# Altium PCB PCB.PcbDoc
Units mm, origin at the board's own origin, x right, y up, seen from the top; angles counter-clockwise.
Board outline 65 x 50 mm, 2 copper layers (Top Layer, Bottom Layer); 114 components, 86 nets, 390 pads, 295 vias.
Unrouted connection lines stored in the file: 2.
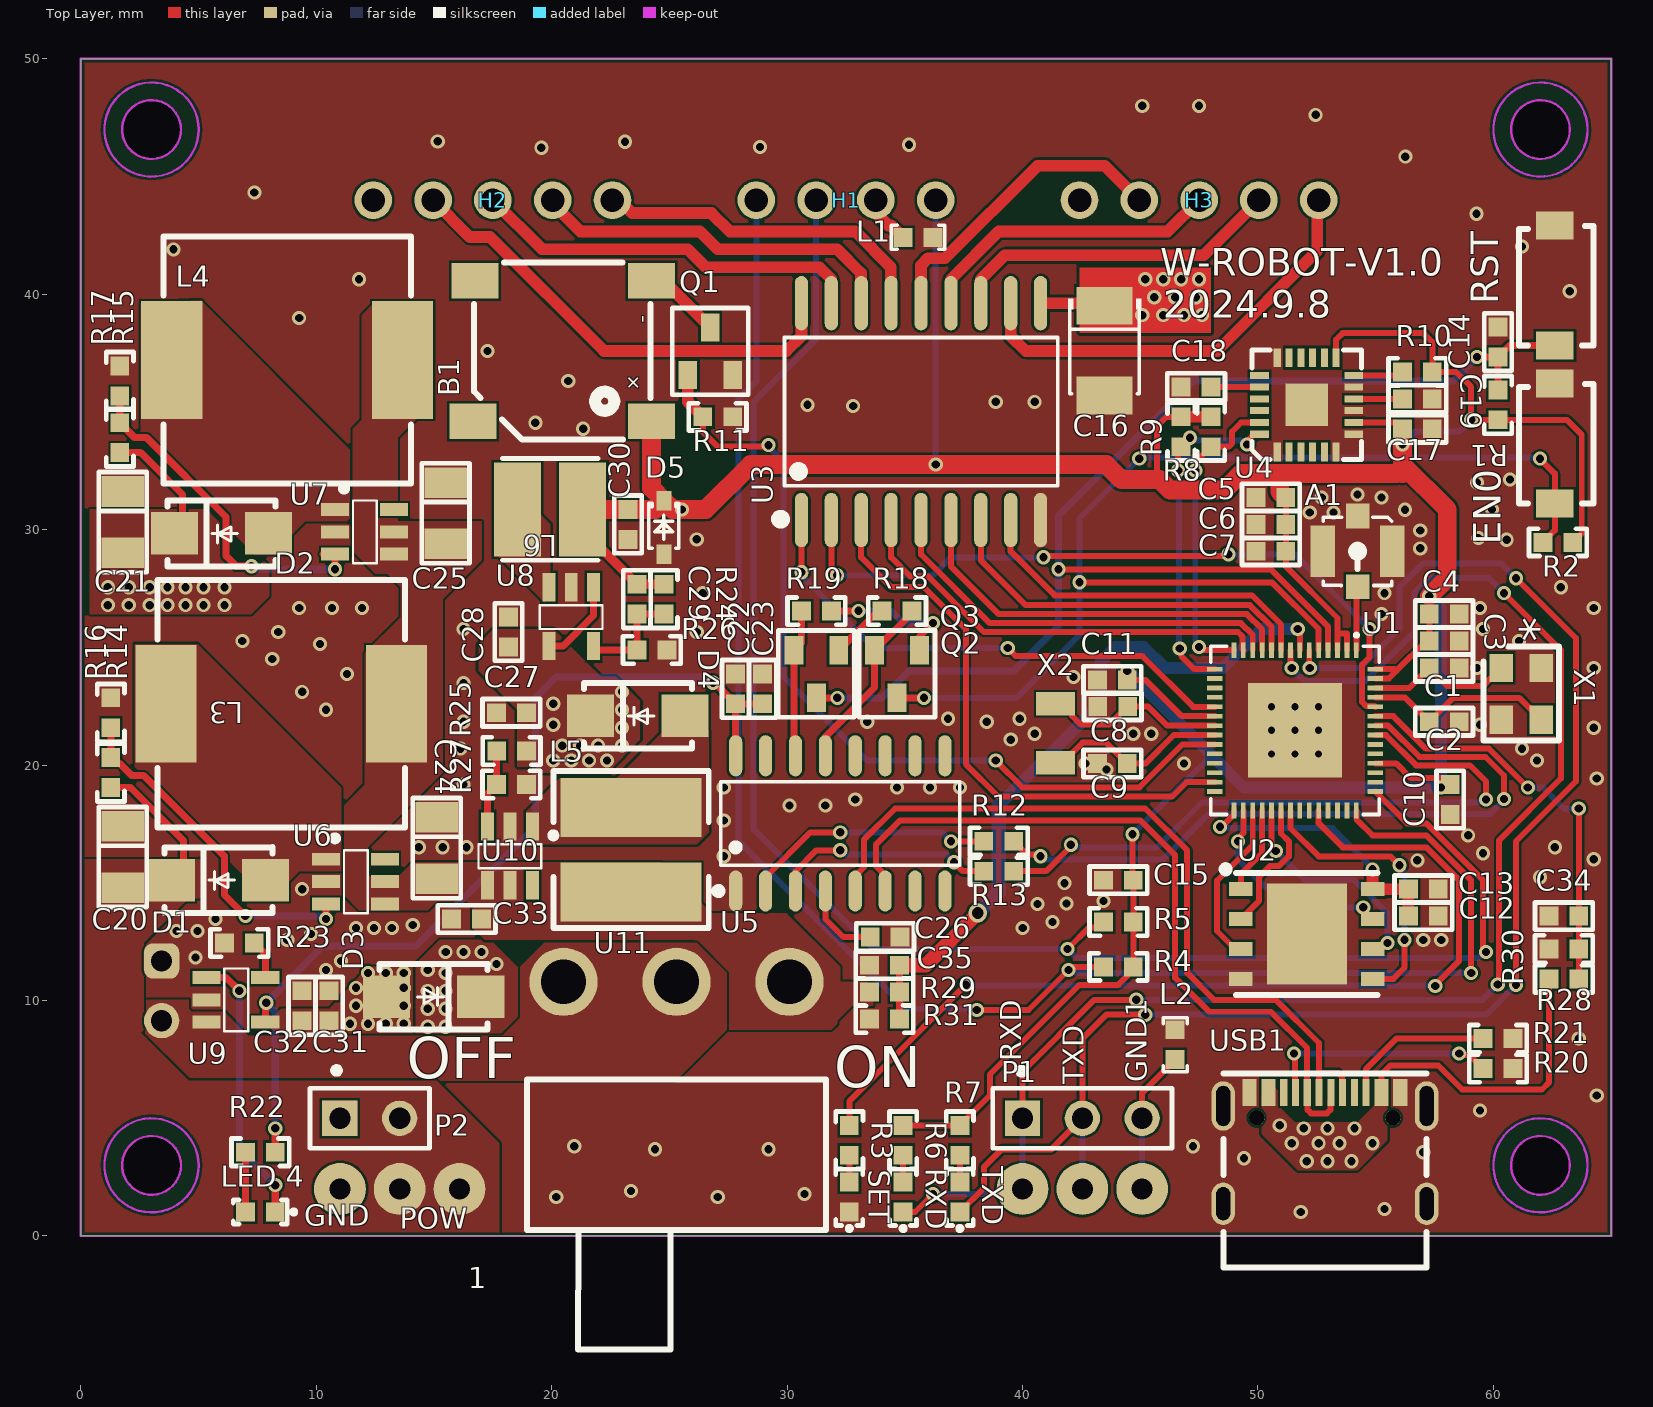
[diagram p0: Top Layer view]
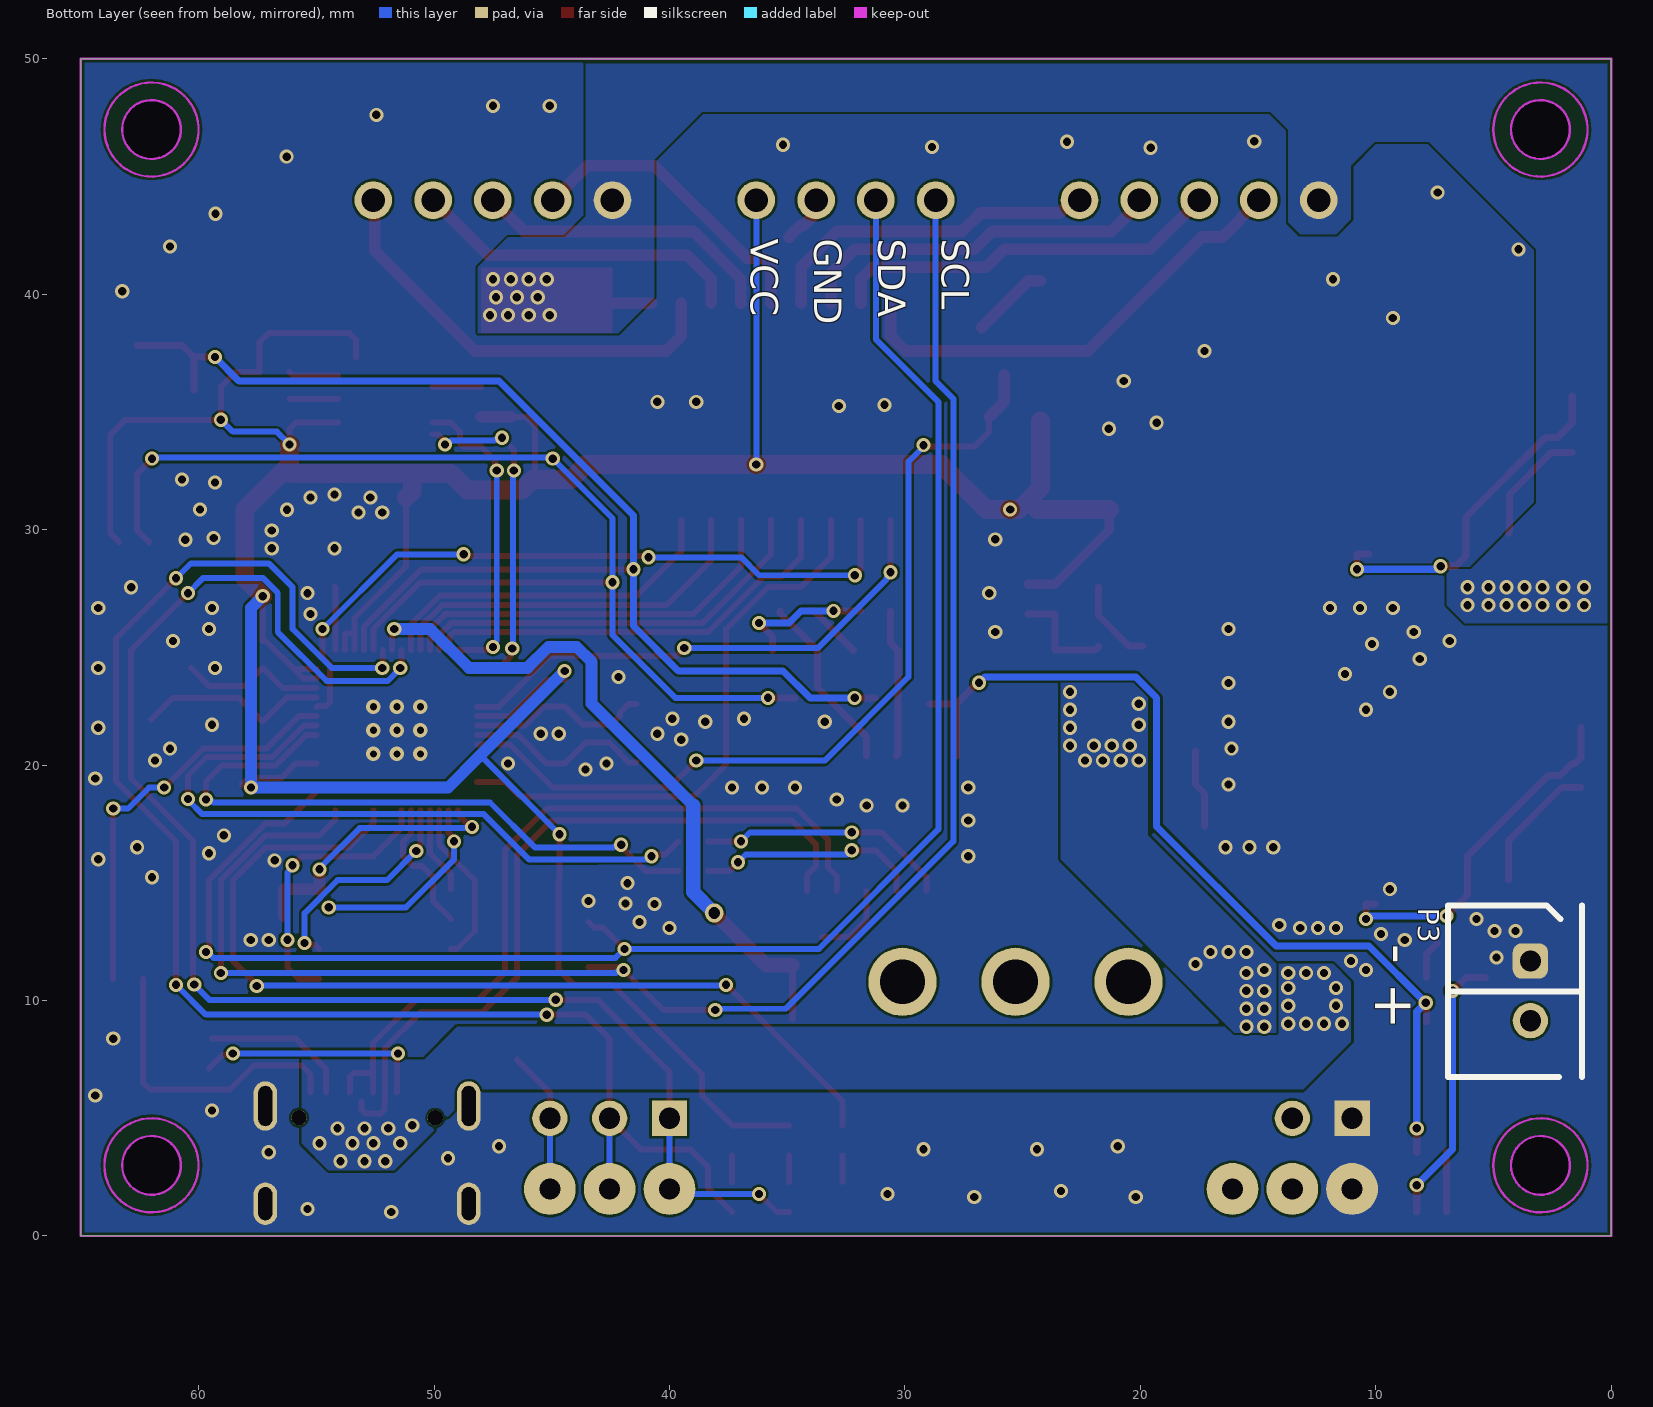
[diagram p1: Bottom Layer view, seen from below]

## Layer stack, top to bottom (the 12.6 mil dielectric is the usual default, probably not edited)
Top Solder: solder mask 0.0102, Solder Resist, Dk 3.5
Top Layer: signal copper 0.0356
Dielectric 1: dielectric 0.32, FR-4, Dk 4.8
Bottom Layer: signal copper 0.0356
Bottom Solder: solder mask 0.0102, Solder Resist, Dk 3.5

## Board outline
0,0 0,50 65,50 65,0
cut-out: 60.75,47 ccw(c62,47) 62,45.75 ccw(c62,47) 63.25,47 ccw(c62,47) 62,48.25 ccw(c62,47)
cut-out: 60.75,3 ccw(c62,3) 62,1.75 ccw(c62,3) 63.25,3 ccw(c62,3) 62,4.25 ccw(c62,3)
cut-out: 60.75,3 ccw(c62,3) 62,1.75 ccw(c62,3) 63.25,3 ccw(c62,3) 62,4.25 ccw(c62,3)
cut-out: 60.75,3 ccw(c62,3) 62,1.75 ccw(c62,3) 63.25,3 ccw(c62,3) 62,4.25 ccw(c62,3)
cut-out: 1.75,3 ccw(c3,3) 3,1.75 ccw(c3,3) 4.25,3 ccw(c3,3) 3,4.25 ccw(c3,3)
cut-out: 1.75,47 ccw(c3,47) 3,45.75 ccw(c3,47) 4.25,47 ccw(c3,47) 3,48.25 ccw(c3,47)

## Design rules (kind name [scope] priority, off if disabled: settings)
Clearance [All] p1: gap=0.1 ignorepadtopadclearanceinfootprint=FALSE except(0: Arc-Hole Track-Hole SMDPad-Hole THPad-Hole Via-Hole Fill-Hole Poly-Hole Region-Hole Text-Hole; 0.102: Arc-Arc Arc-Track Arc-SMDPad Arc-THPad Track-Track Track-SMDPad Track-THPad SMDPad-SMDPad SMDPad-THPad THPad-THPad; 0.127: Arc-Via Track-Via SMDPad-Via SMDPad-Text THPad-Via Via-Via; 0.254: Arc-Text Track-Text THPad-Text Via-Text Fill-Text Poly-Text Region-Text Text-Text)
DiffPairsRouting [All] p1: maxlimit=0.254 minlimit=0.254 mostfreqgap=0.254 toplayer_minwidth=0.2 toplayer_maxwidth=0.381 toplayer_prefwidth=0.381 bottomlayer_minwidth=0.2 bottomlayer_maxwidth=0.381 bottomlayer_prefwidth=0.381 maxuncoupledlength=12.7
HoleSize [All] p1: absolutevalues=TRUE maxlimit=30 minlimit=0.025 maxpercent=80.000 minpercent=20.000
HoleToHoleClearance [All] p1: gap=0.152 allowstackedmicrovias=TRUE
MinimumSolderMaskSliver [All] p1: minsoldermaskwidth=0
PlaneClearance [All] p1: clearance=0.254
PlaneConnect [All] p1: planeconnectstyle=Direct reliefexpansion=0.508 reliefentries=4 reliefconductorwidth=0.254 reliefairgap=0.254
PolygonConnect [All] p1: connectstyle=Direct reliefconductorwidth=0.254 reliefentries=4 polygonreliefangle="90 Angle" airgapwidth=0.254
RoutingVias [All] p1: holewidth=0.711 width=1.27 viastyle="Through Hole" minholewidth=0.3 minwidth=0.5 maxholewidth=30 maxwidth=30
SilkToSilkClearance [All] p1: silktosilkclearance=0
SilkToSolderMaskClearance [IsPad] p1: minsilkscreentomaskgap=0 clearancetoexposedcopper=TRUE
SolderMaskExpansion [All] p1: expansion=0.102 istentingtop=FALSE
Width [All] p1: maxlimit=3 minlimit=0.1 preferedwidth=0.254
22 further rules are at their usual default settings.

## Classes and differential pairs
component class Sheet3-USB: C20 C21 C22 C23 C24 C25 C26 C27 C28 C29 C30 C31 C32 C33 C34 C35 D1 D2 D3 D4 D5 L3 L4 L5 L6 "LED 4" P3 Q2 Q3 R12 R13 R14 R15 R16 R17 R18 R19 R20 R21 R22 R23 R24 R25 R26 R27 R28 R29 R30 R31 U5 U6 U7 U8 U9 U10 U11 USB1
component class Sheet2-control: 1 B1 C15 C16 C17 C18 C19 GND GND1 H1 H2 H3 L1 L2 P1 P2 POW Q1 R4 R5 R6 R7 R8 R9 R10 R11 RXD TXD U3 U4
component class Sheet1-MCU: A1 C1 C2 C3 C4 C5 C6 C7 C8 C9 C10 C11 C12 C13 C14 EN0 R1 R2 R3 RST SET U1 U2 X1 X2
differential pair IO: +IO_P -IO_N
differential pair CH340: +CH340_P -CH340_N

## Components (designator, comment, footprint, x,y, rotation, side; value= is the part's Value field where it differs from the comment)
1 "pogopin" pogopin 16.08,2 r0 top locked
A1 "ANT-IPEX" IPEX-SMD_HC-RF-IPEX0303-01 54.229,29.083 r0 top locked
B1 "BUZZER1" BUZ-SMD_GSC7525RA 20.447,37.592 r180 top
C1 "15pF" CC1608-0603 57.912,24.13 r180 top
C2 "15pF" CC1608-0603 57.912,21.844 r180 top
C3 "1uF" CC1608-0603 57.912,25.273 r180 top
C4 "100nF" CC1608-0603 57.912,26.416 r180 top
C5 "1uF" CC1608-0603 50.546,31.369 r0 top
C6 "100nF" CC1608-0603 50.546,30.226 r0 top
C7 "100nF" CC1608-0603 50.546,29.083 r0 top
C8 "12.5pF" CC1608-0603 43.831,22.495 r0 top
C9 "12.5pF" CC1608-0603 43.815,20.066 r0 top
C10 "100NF" CC1608-0603 58.166,18.542 r90 top
C11 "100NF" CC1608-0603 43.815,23.622 r0 top
C12 "1uF" CC1608-0603 57.023,13.589 r180 top
C13 "100NF" CC1608-0603 57.023,14.732 r180 top
C14 "1uF/NC" CC1608-0603 60.198,37.973 r270 top
C15 "100NF 50V" CC1608-0603 44.069,15.113 r0 top
C16 "100uF" TAN-B_3528 43.561,37.592 r270 top
C17 "100NF 50V" CC1608-0603 56.769,34.29 r180 top
C18 "2.2UF" CC1608-0603 47.371,36.068 r180 top
C19 "100NF" CC1608-0603 56.769,35.56 r180 top
C20 "22uF" TAN-A-1206 1.778,16.129 r270 top
C21 "22uF" TAN-A-1206 1.778,30.353 r270 top
C22 "1uF" CC1608-0603 27.813,23.241 r270 top
C23 "100NF" CC1608-0603 28.956,23.241 r270 top
C24 "22uF" TAN-A-1206 15.113,16.51 r270 top
C25 "22uF" TAN-A-1206 15.494,30.734 r270 top
C26 "100NF" CC1608-0603 34.163,12.7 r180 top
C27 "22uF" CC1608-0603 18.288,22.225 r180 top
C28 "10uF" CC1608-0603 18.161,25.654 r270 top
C29 "22PF" CC1608-0603 23.622,27.051 r90 top
C30 "10uF" CC1608-0603 23.241,30.226 r90 top
C31 "1uF" CC1608-0603 10.541,9.779 r270 top
C32 "100NF" CC1608-0603 9.398,9.779 r270 top
C33 "22uF" CC1608-0603 16.383,13.462 r0 top
C34 "100NF" CC1608-0603 62.992,13.589 r0 top
C35 "100NF" CC1608-0603 34.135,11.502 r0 top
D1 "SS34" "DO-214 AA" 5.842,15.113 r0 top
D2 "SS34" "DO-214 AA" 5.969,29.845 r0 top
D3 "SS34" "DO-214 AA" 14.986,10.16 r180 top
D4 "SS34" "DO-214 AA" 23.654,22.098 r0 top
D5 "PESD3V3L1BA" SOD-323 24.765,30.099 r270 top
EN0 "KEY 3*4" "KEY 3*4" 62.611,31.115 r90 top
GND "pogopin" pogopin 11,2 r0 top locked
GND1 "pogopin" pogopin 45.08,2 r0 top locked
H1 "Header_4P_Curved" HEADER_2_54_4PW 36.31,44 r180 top locked
H2 "Header_5P_Curved" HEADER_2_54_5PW 22.58,44 r180 top locked
H3 "Header_5P_Curved" HEADER_2_54_5PW 52.58,44 r180 top locked
L1 "68nH 200mA" Inductor-0603 35.56,42.418 r180 top
L2 "68nH 200mA" Inductor-0603 46.482,8.128 r270 top
L3 "22UH" CDRH104R 8.509,22.606 r180 top locked
L4 "22UH" CDRH104R 8.763,37.211 r180 top
L5 "10uH" Inductor-6045 23.368,14.605 r180 top
L6 "1uH" Inductor-4018 19.939,30.861 r0 top
"LED 4" "LED 0603" "LED 0603" 7.62,1.016 r0 top
P1 "Header 3" HDR1X3 40,5 r0 top locked
P2 "Header 2" HDR1X2 11,5 r0 top locked
P3 "Header 2" HX2.54-2 3.429,11.684 r270 bottom locked
POW "pogopin" pogopin 13.54,2 r0 top locked
Q1 "SI2302" SOT-23 25.781,36.576 r0 top
Q2 "S8050" SOT-23 32.192,24.88 r180 top
Q3 "S8050" SOT-23 35.621,24.88 r180 top
R1 "10K/NC" CR1608-0603 60.198,35.306 r270 top
R2 "10K" CR1608-0603 62.738,29.464 r0 top
R3 "2K" CR1608-0603 32.639,4.064 r270 top
R4 "2K" CR1608-0603 44.069,11.43 r180 top
R5 "2K" CR1608-0603 44.069,13.335 r180 top
R6 "4.7K" CR1608-0603 34.925,4.064 r270 top
R7 "4.7K" CR1608-0603 37.338,4.064 r270 top
R8 "2K" CR1608-0603 48.006,34.163 r270 top
R9 "2K" CR1608-0603 46.736,34.163 r270 top
R10 "4.7K" CR1608-0603 56.769,36.703 r180 top
R11 "33KR" CR1608-0603 27.051,34.798 r0 top
R12 "470R" CR1608-0603 38.989,16.764 r0 top
R13 "470R" CR1608-0603 38.989,15.494 r0 top
R14 "33KR" CR1608-0603 1.27,19.685 r90 top
R15 "33KR" CR1608-0603 1.651,33.909 r90 top
R16 "2KR" CR1608-0603 1.27,22.225 r90 top
R17 "2KR" CR1608-0603 1.651,36.322 r90 top
R18 "12K/10K" CR1608-0603 34.671,26.543 r180 top
R19 "12K/10K" CR1608-0603 31.242,26.543 r0 top
R20 "5.1K" CR1608-0603 60.198,7.112 r180 top
R21 "5.1K" CR1608-0603 60.198,8.382 r180 top
R22 "1K" CR1608-0603 7.62,3.556 r180 top
R23 "2K" CR1608-0603 6.731,12.446 r180 top
R24 "100K" CR1608-0603 24.765,27.051 r270 top
R25 "78.7KR" CR1608-0603 18.296,20.601 r0 top
R26 "22.1K" CR1608-0603 24.257,24.892 r0 top
R27 "10KR" CR1608-0603 18.288,19.177 r180 top
R28 "10K" CR1608-0603 62.992,10.922 r180 top
R29 "10K" CR1608-0603 34.135,10.359 r180 top
R30 "10K" CR1608-0603 62.992,12.192 r0 top
R31 "10K" CR1608-0603 34.135,9.216 r0 top
RST "KEY 3*4" "KEY 3*4" 62.611,37.826 r90 top
RXD "LED 0603" "LED 0603" 34.925,1.651 r270 top
RXD "pogopin" pogopin 40,2 r0 top locked
SET "LED 0603" "LED 0603" 32.639,1.651 r270 top
TXD "LED 0603" "LED 0603" 37.338,1.651 r270 top
TXD "pogopin" pogopin 42.54,2 r0 top locked
U1 "ESP32-S3" QFN-56 51.578,21.479 r270 top locked
U2 "W25Q64JVPIQ" WSON-8 52.076,12.827 r270 top locked
U3 "ULN2803A-DWM" SOP-18 35.687,35.019 r0 top locked
U4 "MPU6050" "QFN24 - duplicate" 52.07,35.306 r90 top
U5 "CH340C" SOP-16 32.258,17.526 r0 top
U6 "MT3608" SOT23-6 11.684,15.113 r270 top
U7 "MT3608" SOT23-6 12.065,29.972 r270 top
U8 "SY8089A1AAC" SOT23-5 19.873,27.559 r0 top
U9 "TP4054" SOT23-5 5.334,9.078 r90 top
U10 "SX1308" SOT23-6 18.288,16.129 r180 top
U11 "HX SS12D10G4" SW-TH_3P-SS12D06 25.299,10.795 r0 top locked
USB1 "Tpye-c 16P" "TYPE-C 16P" 55.734,5.021 r0 top locked
X1 "3225_40M" XTAL-3225 62.025,24.13 r270 top
X2 "32.768kKHz" XTAL-3215 41.402,22.606 r270 top

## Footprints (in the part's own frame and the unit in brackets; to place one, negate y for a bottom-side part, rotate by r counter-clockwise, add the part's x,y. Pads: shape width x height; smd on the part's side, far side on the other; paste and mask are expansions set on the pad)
BUZ-SMD_GSC7525RA [mm]
  rect 2x1.5 smd paste+0 mask+0.051: 1(-3.795,2.98) 2(-3.795,-2.98) 3(3.705,-2.98) 3(3.795,2.98)
  silkscreen extent -3.75,-3.75 3.76,3.76, body extent -3.81,-3.81 3.69,3.69, height 2.5
CC1608-0603 [mm]
  rect 0.8x0.8 smd: 1(-0.635,0) 2(0.635,0)
  silkscreen extent -1.23,-0.58 1.23,0.58, body extent -0.8,-0.4 0.8,0.4, height 0.3
CDRH104R [mm]
  rect 2.6x5 smd paste+0 mask+0.05: 1(-4.9,0) 2(4.9,0)
  silkscreen extent -5.25,-5.25 5.25,5.25, body extent -5.19,-5.14 5.31,5.16, height 4
CR1608-0603 [mm]
  rect 0.8x0.8 smd: 1(-0.635,0) 2(0.635,0)
  silkscreen extent -1.23,-0.58 1.23,0.58, body extent -0.8,-0.4 0.8,0.4, height 0.45
"DO-214 AA" [mm] "SMB"
  rect 2x1.8 smd: 1(-2,0) 2(2,0)
  silkscreen extent -2.3,-1.4 2.3,1.4, body extent -2.83,-1.8 2.57,1.8, height 2.4
HDR1X2 [mm] "Connector; Header; 2 Position"
  rect 1.5x1.5 hole 0.9: 1(0,0)
  round 1.5 hole 0.9: 2(2.54,0)
  silkscreen extent -1.27,-1.27 3.81,2.17, body extent -1.27,-1.27 3.81,1.27, height 8.54
HDR1X3 [mm] "Connector; Header; 3 Position"
  rect 1.5x1.5 hole 0.9: 1(0,0)
  round 1.5 hole 0.9: 2(2.54,0) 3(5.08,0)
  silkscreen extent -1.27,-1.27 6.35,2.14, body extent -1.27,-1.27 6.35,1.27, height 8.54
HEADER_2_54_4PW [mm] "3P弯针"
  round 1.6 hole 1: 1(0,0) 2(2.54,0) 3(5.08,0) 4(7.62,0)
  body extent -2.54,-7.48 10.16,0.38, height 5.8
HEADER_2_54_5PW [mm] "6P弯针"
  round 1.6 hole 1: 1(0,0) 2(2.54,0) 3(5.08,0) 4(7.62,0) 5(10.16,0)
  body extent -2.64,-7.35 12.57,0.51, height 5.8
HX2.54-2 [mm] "两针白色插座（已加焊）"
  rrect50% 1.5x1.5 hole 0.9: 1(0,0)
  round 1.5 hole 0.9: 2(2.54,0)
  silkscreen extent -2.36,-3.5 4.94,2.2, body extent -2.48,-3.55 5.02,2.45, height 7
Inductor-0603 [mm]
  rect 0.8x0.8 smd: 1(-0.635,0) 2(0.635,0)
  silkscreen extent -1.14,-0.51 1.14,0.51, body extent -0.8,-0.43 0.8,0.43, height 0.48
Inductor-4018 [mm]
  rect 2x4 smd paste+0 mask+0.051: 1(-1.397,0) 2(1.373,0)
  silkscreen extent -2.03,-2.16 2.03,2.16, body extent -2,-2 2,2, height 1.8
Inductor-6045 [mm] "电感"
  rect 6x2.5 smd: 1(0,0) 2(0,-3.6)
  silkscreen extent -3.3,-5.14 3.3,1.52, body extent -3,-4.93 3,1.37, height 4.5
IPEX-SMD_HC-RF-IPEX0303-01 [mm] "孔径2.0mm"
  rect 1x1.05 smd: 1(0,-1.5) 4(0,1.5)
  rect 1.05x2.2 smd: 2(1.475,0) 3(-1.475,0)
  silkscreen extent -1.45,-1.45 1.45,1.45, body extent -1.5,-1.55 1.5,1.55, height 1.25
"KEY 3*4" [mm]
  rect 1.2x1.6 smd: 1(0,0) 2(5.1,0)
  silkscreen extent 0,-1.65 5.08,1.52, body extent 0.25,-1.71 4.7,1.46, height 2.01
"LED 0603" [mm]
  rect 0.8x0.8 smd: 1(-0.635,0) 2(0.635,0)
  silkscreen extent -1.14,-0.51 1.48,0.51, body extent -0.8,-0.4 0.8,0.4, height 0.6
pogopin [mm]
  round 2.2 hole 0.9: 1(0,0)
  body extent -1,-1 1,1, height 10
"QFN24 - duplicate" [mm]
  rect 0.8x0.3 smd: 1(-2,1.25) 2(-2,0.75) 3(-2,0.25) 4(-2,-0.25) 5(-2,-0.75) 6(-2,-1.25) 13(2,-1.25) 14(2,-0.75) 15(2,-0.25) 16(2,0.25) 17(2,0.75) 18(2,1.25)
  rect 1.8x1.8 smd: 1(0.005,0)
  rect 0.3x0.8 smd: 7(-1.25,-2) 8(-0.75,-2) 9(-0.25,-2) 10(0.25,-2) 11(0.75,-2) 12(1.25,-2) 19(1.25,2) 20(0.75,2) 21(0.25,2) 22(-0.25,2) 23(-0.75,2) 24(-1.25,2)
  silkscreen extent -2.32,-2.32 2.32,2.32, body extent -2,-2 2.01,2, height 0.9
QFN-56 [mm]
  rect 0.665x0.2 smd paste-100 mask+0.051: 1(-3.407,2.6) 2(-3.407,2.2) 3(-3.407,1.8) 4(-3.407,1.4) 5(-3.407,1) 6(-3.407,0.6) 7(-3.407,0.2) 8(-3.407,-0.2) 9(-3.407,-0.6) 10(-3.407,-1) 11(-3.407,-1.4) 12(-3.407,-1.8) 13(-3.407,-2.2) 14(-3.407,-2.6) 29(3.408,-2.6) 30(3.408,-2.2) 31(3.408,-1.8) 32(3.408,-1.4) 33(3.408,-1) 34(3.408,-0.6) 35(3.408,-0.2) 36(3.408,0.2) 37(3.408,0.6) 38(3.408,1) 39(3.408,1.4) 40(3.408,1.8) 41(3.408,2.2) 42(3.408,2.6)
  rect 0.2x0.665 smd paste-100 mask+0.051: 15(-2.6,-3.407) 16(-2.2,-3.407) 17(-1.8,-3.407) 18(-1.4,-3.407) 19(-1,-3.407) 20(-0.6,-3.407) 21(-0.2,-3.407) 22(0.2,-3.407) 23(0.6,-3.407) 24(1,-3.407) 25(1.4,-3.407) 26(1.8,-3.407) 27(2.2,-3.407) 28(2.6,-3.407) 43(2.6,3.408) 44(2.2,3.408) 45(1.8,3.408) 46(1.4,3.408) 47(1,3.408) 48(0.6,3.408) 49(0.2,3.408) 50(-0.2,3.408) 51(-0.6,3.408) 52(-1,3.408) 53(-1.4,3.408) 54(-1.8,3.408) 55(-2.2,3.408) 56(-2.6,3.408)
  rect 4x4 smd paste-100 mask+0.051: 57(0,0)
  silkscreen extent -4.11,-3.58 3.58,3.58, body extent -3.51,-3.52 3.51,3.49, height 0.9
SOD-323 [mm]
  rect 0.83x0.63 smd paste+0 mask+0.05: 1(-1.14,0) 2(1.14,0)
  silkscreen extent -1.02,-0.64 0.89,0.64, body extent -1.27,-0.68 1.33,0.68, height 1.1
SOP-16 [mm]
  oval 0.56x1.745 smd: 1(-4.445,-2.873) 2(-3.175,-2.873) 3(-1.905,-2.873) 4(-0.635,-2.873) 5(0.635,-2.873) 6(1.905,-2.873) 7(3.175,-2.873) 8(4.445,-2.873) 9(4.445,2.873) 10(3.175,2.873) 11(1.905,2.873) 12(0.635,2.873) 13(-0.635,2.873) 14(-1.905,2.873) 15(-3.175,2.873) 16(-4.445,2.873)
  silkscreen extent -5.33,-3.02 5.08,1.77, body extent -4.99,-3.09 4.99,3.14, height 1.59
SOP-18 [mm]
  oval 0.56x2.31 smd paste+0 mask+0.051: 1(-5.08,-4.605) 2(-3.81,-4.605) 3(-2.54,-4.605) 4(-1.27,-4.605) 5(0,-4.605) 6(1.27,-4.605) 7(2.54,-4.605) 8(3.81,-4.605) 9(5.08,-4.605) 10(5.08,4.605) 11(3.81,4.605) 12(2.54,4.605) 13(1.27,4.605) 14(0,4.605) 15(-1.27,4.605) 16(-2.54,4.605) 17(-3.81,4.605) 18(-5.08,4.605)
  silkscreen extent -6.17,-4.77 5.8,3.15, body extent -5.78,-5.09 5.78,5.22, height 2.61
SOT23-5 [mm] "适用于MIC5205"
  rect 0.55x1.2 smd: 1(1.905,0) 2(0.955,0) 3(0.005,0) 4(0.005,-2.5) 5(1.905,-2.5)
  silkscreen extent -0.38,-1.78 2.29,-0.76, body extent -0.6,-2.82 2.5,0.38, height 1.45
SOT23-6 [mm]
  rect 0.55x1.2 smd: 1(-0.889,-1.27) 2(0.061,-1.27) 3(1.011,-1.27) 4(1.011,1.23) 5(0.061,1.23) 6(-0.889,1.23)
  silkscreen extent -1.9,-1.02 1.4,0.51, body extent -1.39,-1.4 1.51,1.4, height 1.45
SOT-23 [mm]
  rect 0.8x1.2 smd: 1(0,0) 2(1.905,0) 3(0.95,2.02)
  silkscreen extent -0.66,-0.84 2.57,2.84, body extent -0.61,-0.23 2.39,2.27, height 1.05
SW-TH_3P-SS12D06 [mm]
  round 2.9 hole 1.9 paste+0 mask+0.051: 1(-4.8,0) 2(0,0) 3(4.8,0)
  silkscreen extent -6.35,-15.62 6.35,-4.15, body extent -6.35,-15.68 6.35,-4.19, height 6.7
TAN-A-1206 [mm]
  rect 1.3x1.8 smd: 1(-1.27,0) 2(1.333,0)
  silkscreen extent -2.1,-1.02 2.16,1.02, body extent -1.66,-0.8 1.54,0.8, height 1.6
TAN-B_3528 [mm] "钽电容小封装"
  rect 1.607x2.376 smd: 1(-1.926,-0.075) 2(1.897,-0.075)
  silkscreen extent -2.22,-1.63 1.81,1.48, body extent -1.98,-1.59 1.72,1.34, height 2.03
"TYPE-C 16P" [mm]
  oval 1x2.099 hole 0.6 slot 1.7 at 90 deg: 1(-7.21,0.5) 2(1.43,0.5)
  oval 1x1.799 hole 0.6 slot 1.4 at 90 deg: 3(-7.21,-3.65) 4(1.43,-3.65)
  rect 0.6x1.15 smd: A1B12(-6.09,1.075) A4B9(-5.29,1.075) B1A12(0.31,1.075) B4A9(-0.49,1.075)
  rect 0.3x1.15 smd: A5(-4.14,1.075) A6(-3.14,1.075) A7(-2.64,1.075) A8(-1.64,1.075) B5(-1.14,1.075) B6(-2.14,1.075) B7(-3.64,1.075) B8(-4.64,1.075)
  round 0.65 hole 0.65 unplated: ""(-5.78,0) ""(0,0)
  silkscreen extent -7.21,-6.37 1.43,1.89, body extent -7.31,-6 1.63,0.9, height 3.18
WSON-8 [mm]
  rect 0.6x1 smd paste+0 mask+0.051: 1(-1.905,-2.8) 2(-0.635,-2.8) 3(0.635,-2.8) 4(1.905,-2.8) 5(1.905,2.8) 6(0.635,2.8) 7(-0.635,2.8) 8(-1.905,2.8)
  rect 4.3x3.4 smd paste+0 mask+0.051: 9(0,0)
  silkscreen extent -2.9,-3.6 2.6,3, body extent -2.5,-3 2.5,3, height 0.7
XTAL-3215 [mm]
  rect 1x1.65 smd: 1(0,0) 2(2.5,0)
  body extent -0.33,-0.75 2.87,0.75, height 0.8
XTAL-3225 [mm]
  rect 1.2x1 smd: 1(0,-1.7) 2(2.2,-1.7) 3(2.2,0) 4(0,0)
  silkscreen extent -0.91,-2.44 3.07,0.76, body extent -0.43,-2.15 2.77,0.35, height 0.61

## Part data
1 GND GND1 POW RXD TXD: "插板式顶针 连接器弹簧天线插针SMT触点测试铜针双弹贴片式"
A1: "贴片封装的天线 封装类型为IPEX"
B1: "2700Hz", Manufacturer=INGHAi(赢海), Manufacturer Part=GSC7525RA-16R2700
C1 C2 C3 C4 C5 C6 C7 C8 C9 C10 C11 C12 C13 C14 C15 C17 C18 C19 C22 C23 C26 C28 C29 C30 C31 C32 C33 C34 C35: library part "Cap Chip 0603", "0603封装的电容"
C16: library part "CAP TAN-B-3528", "钽电容"
C20 C21 C24 C25: library part "CAP TAN-A-1206", "钽电容"
C27: library part "Chip capacitor", "贴片电容"
D1 D2 D3 D4: "肖特基二极管"
D5: "SOD-323 3.3V 双向ESD防静电二极管保护芯片", JLCPCB Part Class="Extended Part", Manufacturer=MDD, Manufacturer Part=SMAJ6.5CA
EN0 RST: "轻触开关按键"
H1: "弯的4P排针"
H2 H3: "弯的6P排针"
L1 L2: library part Inductor-0603, "贴片电感 0603封装"
L3 L4: library part Inductor-CDRH104R, "贴片电感 CDRH104R 封装"
L5: library part Inductor-6045, "6045封装 线绕SMD功率电感"
L6: library part Inductor-4018, "贴片电感 1206封装"
P1: "Header, 3-Pin"
P2 P3: "Header, 2-Pin"
Q1: "N沟道  / 漏源电压(Vdss) 20V  / 连续漏极电流(Id) 2.8A  / 功率(Pd) 900mW  / 导通电阻(RDS(on)@Vgs,Id) 55mΩ@4.5V,2.8A  / 阈值电压(Vgs(th)@Id) 1.2V@250uA  / 输入电容(Ciss@Vds) 260pF@10V", JLCPCB Part Class="Extended Part", Manufacturer=TWGMC(台湾迪嘉), Manufacturer Part=SI2306
Q2 Q3: Manufacturer=SALLTECH(萨瑞)
R1 R2 R3 R4 R5 R6 R7 R8 R9 R10 R12 R13 R18 R19 R20 R21 R22 R23 R24 R26 R28 R29 R30 R31: library part "Resistor Chip 0603", "0603封装电阻"
R11 R14 R15 R16 R17 R25 R27: library part "Chip resistor", "贴片电阻"
U1: JLCPCB Part Class="Extended Part", Manufacturer=ESPRESSIF(乐鑫)
U2: library part W25Q128JVPIQ, JLCPCB Part Class="Extended Part", Manufacturer=WINBOND(华邦)
U3: library part ULN2803A, "UMW ULN2803A SOP-18 达林顿阵列功率驱动集成电路芯片", JLCPCB Part Class="Extended Part", Manufacturer=HGC(华冠), Manufacturer Part=ULN2803ADWM/TR
U4: "陀螺仪"
U5: JLCPCB Part Class="Extended Part", Manufacturer=WCH(南京沁恒)
U6 U7: "• 2V to 24V Input Voltage / • 1.2MHz Fixed Switching Frequency / • Internal 4A Switch Current Limit / • Adjustable Output Voltage / • Internal Compensation / • Up to 28V Output VoltagE"
U8: "SY8089A1是一种高效率的1.5MHz同步降压DC/DC稳压器，能够提供高达输出电流2A。它可以在2.5V到5.5V的宽输入电压范围内工作，集成了主开关和同步开关，具有极低的RDS(ON)，最大限度地减少了导通损耗。 / 输出电压纹波小，外接电感小，电容器尺寸小 / 1.5MHz开关频率。"
U9: "迷你充电IC SOT-23-5"
U10: "SOT23-6 升压芯片"
U11: library part SW-TH_3P-SS12D06, BOM_JLCPCB Part Class="Extended Part", BOM_Manufacturer=hanxia(韩下)
USB1: "16P 封装的TYPE -c接口 4固定插脚 双向"
X1: library part "XTAL 3225", "3225封装的晶振"
X2: library part "XTAL 3215 32.768kKHz", "3215封装的时钟晶振"

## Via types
v1: diameter 0.6, hole 0.35, Top Layer to Bottom Layer, tented both sides, 285 vias
v2: diameter 0.61, hole 0.305, Top Layer to Bottom Layer, tented both sides, 9 vias
v3: diameter 0.8, hole 0.5, Top Layer to Bottom Layer, tented both sides, 1 vias

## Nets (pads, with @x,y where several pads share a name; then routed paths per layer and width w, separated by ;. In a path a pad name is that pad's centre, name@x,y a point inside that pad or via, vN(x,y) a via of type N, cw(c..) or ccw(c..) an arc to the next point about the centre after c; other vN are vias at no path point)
3.3V: B1.1 C3.2 C4.2 C5.2 C6.2 C7.2 C10.2 C11.2 C15.2 C17.2 C29.2 C30.2 D5.1 H1.1 L6.2 R1.2 R2.2 R4.1 R5.1 R6.1 R7.1 R8.1 R9.1 R10.1 R24.1 U1.2 U1.3 U1.20 U1.46 U1.55 U1.56 U4.8 U4.13 | length 166.5
  Top Layer w0.254: R6.1 R7.1 38.608,5.969 38.608,6.858 42.418,10.668 44.069,10.668 44.704,11.303 R4.1 R5.1 C15.2 44.672,15.145 v1(44.672,17.064) ; v1(44.45,24.003) C11.2 45.212,23.622 46.755,22.079 U1.20 ; 45.72,32.131 45.72,34.417 46.101,34.798 R9.1 ; C5.2 C6.2 51.181,28.448 53.378,26.251 U1.3 ; U4.13 53.32,38.08 53.594,38.354 57.023,38.354 57.404,37.973 R10.1 58.42,36.703 59.055,36.068 v1(59.055,34.671) R1.2 63.119,34.671 63.754,34.036 63.754,29.845 R2.2 ; 53.397,25.597 53.778,25.597 U1.2 ; U4.8 55.868,34.556 C17.2 v1(56.134,33.62) ; U1.46 55.867,20.079 56.496,19.45 57.893,19.45 C10.2 ; U1.55 55.556,23.679 55.88,24.003 ; U1.56 55.804,24.079 55.88,24.003 ; 55.88,32.385 56.134,32.639 ; v1(57.277,27.178) C4.2 C3.2 57.15,25.273 55.88,24.003 ; v1(57.771,19.05) 58.01,19.05 C10.2@58.152,19.191
  Top Layer w0.4: L6.2 21.312,29.996 C29.2 R24.1
  Top Layer w0.5: R9.1 R8.1
  Top Layer w0.8: L6.2 C30.2 24.387,30.861 D5.1 ; B1.1 24.242,31.762 D5.1 ; C5.2 50.927,31.623 50.927,32.385 ; 55.88,32.385 50.927,32.385 ; 56.134,32.385 v1(56.134,33.62) ; 56.134,32.766 58.039,30.861 58.039,27.94 v1(57.277,27.178) ; D5.1 25.143,30.861 v1(25.527,30.861) 26.543,30.861 28.448,32.766 36.302,32.766 v1(36.312,32.776) 36.322,32.766 43.561,32.766 44.196,32.131 45.72,32.131 45.82,32.131 46.266,31.685 48.576,31.685 49.276,32.385 50.927,32.385
  Bottom Layer w0.254: H1.1 36.311,43.999 v1(36.312,32.776) v1(36.312,32.776) ; v1(44.672,17.064) 47.992,20.383 48.069,20.383 ; v1(56.134,33.62) 56.677,34.163 58.547,34.163 v1(59.055,34.671)
  Bottom Layer w0.5: v1(44.45,24.003) 48.069,20.383 49.403,19.05 v1(57.771,19.05) 57.771,26.684 v1(57.277,27.178)
5V: C27.1 C28.2 D3.1 D4.1 R25.2 U8.1 U8.4 | length 3.6
  Top Layer w0.3: U8.4 20.487,25.059 21.778,26.35 U8.1
  other v1: 14.732,8.89 15.494,8.89 14.732,9.652 15.494,9.652 14.732,10.414 15.494,10.414 15.494,11.176 14.732,11.303 17.653,11.557 15.494,12.065 16.256,12.065 17.018,12.065 20.066,20.193 20.828,20.193 21.59,20.193 22.352,20.193 20.447,20.828 21.209,20.828 21.971,20.828 22.987,20.828 22.987,21.59 20.066,21.717 22.987,22.352 20.066,22.606 22.987,23.114
ADC_BAT: C35.2 R29.1 R31.2 U1.7 | length 30
  Top Layer w0.254: v1(51.689,25.781) 51.778,25.692 U1.7
  Top Layer w0.3: R31.2 R29.1 C35.2
  Top Layer w0.6: C35.2 35.886,11.502 v3(38.1,13.716)
  Bottom Layer w0.5: 38.989,18.288 43.307,22.606 43.307,24.384 43.942,25.019 45.144,25.019 46.033,24.13 48.514,24.13 50.165,25.781 v1(51.689,25.781)
  Bottom Layer w0.6: v3(38.1,13.716) 38.989,14.605 38.989,18.288
BAT: C24.2 C25.2 C33.2 L3.1 L4.1 L5.1 R29.2 U6.4 U6.5 U7.4 U7.5 U10.4 U10.5 U11.3
BEEP: Q1.1 R11.1 U1.23 | length 36.9
  Top Layer w0.254: R11.1 26.416,34.163 27.051,33.528 29.145,33.528 v1(29.21,33.593) ; v1(38.862,20.193) 40.005,19.05 44.958,19.05 46.787,20.879 U1.23
  Top Layer w0.5: Q1.1 25.781,35.433 R11.1
  Bottom Layer w0.254: v1(29.21,33.593) 29.21,33.528 29.845,32.893 29.845,23.749 33.401,20.193 v1(38.862,20.193)
CH340_N: U5.6 USB1.A7 USB1.B7 | length 32
  Top Layer w0.254: U5.6 34.163,15.329 33.782,15.71 33.782,16.637 34.798,17.653 45.002,17.653 46.482,16.173 46.482,10.966 47.923,9.525 50.546,9.525 52.086,7.985 52.086,7.62 52.086,6.858 52.086,5.672 52.11,5.648 52.11,5.356 52.258,5.207 52.93,5.207 53.078,5.356 53.078,5.707 USB1.A7@53.086,5.715
CH340_P: U5.5 USB1.A6 USB1.B6 | length 33.2
  Top Layer w0.254: U5.5 32.893,15.292 33.274,15.673 33.274,16.847 34.588,18.161 45.212,18.161 46.99,16.383 46.99,11.176 48.133,10.033 50.756,10.033 52.594,8.195 52.594,6.858 ; USB1.A6 52.594,6.858 ; USB1.B6 53.571,6.119 53.571,6.754 53.404,6.922 52.658,6.922 52.594,6.858
CHIP_PU: C14.2 Q2.3 R1.1 RST.1 U1.4 | length 55.2
  Top Layer w0.254: v1(41.529,28.321) 50.541,28.321 52.978,25.884 U1.4
  Top Layer w0.3: Q2.3 v1(32.131,22.86) ; v1(59.309,37.338) C14.2 ; R1.1 C14.2 ; RST.1 60.686,37.826 C14.2
  Bottom Layer w0.3: v1(32.131,22.86) 34.036,22.86 35.179,24.003 39.624,24.003 41.529,25.908 v1(41.529,28.321) 41.529,30.607 47.244,36.322 58.293,36.322 v1(59.309,37.338)
DTR: Q3.2 R18.1 U5.13 | length 7.7
  Top Layer w0.3: U5.13 31.623,21.209 33.716,23.302 Q3.2 35.306,26.47 R18.1
GND: A1.2 A1.3 A1.4 C1.1 C2.1 C3.1 C4.1 C5.1 C6.1 C7.1 C8.1 C9.1 C10.1 C11.1 C12.1 C13.1 C14.1 C15.1 C16.2 C17.1 C18.2 C19.1 C20.1 C21.1 C22.1 C23.1 C24.1 C25.1 C26.1 C27.2 C28.1 C30.1 C31.1 C32.1 C33.1 C34.1 C35.1 D5.2 EN0.2 GND.1 L1.1 L2.1 P2.1 P3.1 Q1.2 R11.2 R16.2 R17.2 R20.1 R21.1 R23.2 R26.2 R27.1 R30.1 R31.1 RST.2 SET.2 U1.57 U2.4 U2.9 U3.9 U4.1 U4.6 U4.7 U4.9 U4.11 U4.18 U5.1 U6.2 U7.2 U8.2 U9.2 U10.2 USB1.1 USB1.2 USB1.3 USB1.4 USB1.A1B12 USB1.B1A12 X1.2 X1.4
  other v1: 51.816,1.016 55.372,1.143 20.193,1.651 27.051,1.651 30.734,1.778 23.368,1.905 49.403,3.302 57.023,3.556 24.384,3.683 29.21,3.683 20.955,3.81 47.244,3.81 59.436,5.334 64.389,5.969 63.627,8.382 10.414,11.303 11.049,11.684 4.863,11.831 8.763,12.573 57.023,12.573 57.785,12.573 9.779,12.827 4.064,12.954 4.953,12.954 11.684,13.081 12.446,13.081 13.208,13.081 40.005,13.081 14.097,13.208 41.275,13.335 5.715,13.462 40.64,14.097 41.87,14.125 43.434,14.224 9.398,14.732 41.783,14.986 61.976,15.24 56.769,15.956 64.262,16.002 27.305,16.129 59.563,16.256 14.351,16.51 15.367,16.51 16.383,16.51 62.611,16.51 58.928,17.018 27.305,17.653 30.099,18.288 31.623,18.288 32.893,18.542 27.305,19.05 34.671,19.05 36.068,19.05 37.338,19.05 16.256,19.177 64.389,19.431 43.561,19.812 42.672,20.066 46.863,20.066 61.849,20.193 16.129,20.701 61.214,20.701 39.497,21.082 40.513,21.336 44.704,21.336 45.466,21.336 64.262,21.59 59.436,21.717 16.256,21.844 33.401,21.844 38.481,21.844 36.83,21.971 39.878,21.971 10.414,22.352 9.398,23.114 16.256,23.495 42.164,23.749 11.303,23.876 59.309,24.13 64.262,24.13 8.128,24.511 10.16,25.146 6.858,25.273 61.087,25.273 8.382,25.654 26.162,25.654 16.256,25.781 59.563,25.781 55.245,26.416 9.271,26.67 10.668,26.67 11.938,26.67 59.436,26.67 64.262,26.67 26.416,27.305 55.372,27.305 62.865,27.559 54.229,29.21 56.896,29.21 60.565,29.573 26.162,29.591 59.361,29.647 56.896,29.972 52.197,30.734 53.213,30.734 56.248,30.848 59.944,30.861 52.705,31.369 55.245,31.369 54.229,31.496 59.309,32.004 60.706,32.131 21.336,34.29 19.304,34.544 32.805,35.258 30.861,35.306 38.862,35.433 40.513,35.433 20.701,36.322 17.272,37.592 9.271,38.989 63.246,40.132 11.811,40.64 3.937,41.91 61.214,42.037 59.287,43.425 7.366,44.323 56.261,45.847 19.558,46.228 28.842,46.259 35.179,46.355 23.114,46.482 15.157,46.499 52.451,47.625 45.085,48.006 47.498,48.006
  other v2: 50.578,20.479 51.578,20.479 52.578,20.479 50.579,21.479 51.578,21.479 52.578,21.479 50.578,22.479 51.578,22.479 52.578,22.479
GPIO0: EN0.1 Q3.3 R2.1 U1.5 | length 50.4
  Top Layer w0.254: v1(42.418,27.767) 50.592,27.767 52.578,25.781 U1.5 ; v1(61.976,33.02) 62.611,32.385 EN0.1 62.611,29.972 R2.1
  Top Layer w0.3: Q3.3 v1(35.814,22.86)
  Bottom Layer w0.254: v1(35.814,22.86) 39.751,22.86 42.427,25.536 42.427,27.758 v1(42.418,27.767) 42.418,30.48 45.004,33.066 61.93,33.066 v1(61.976,33.02)
  other v1: 44.958,33.02
IIC2_SCL: R8.2 U1.14 U4.23 | length 13.2
  Top Layer w0.254: v1(47.336,32.512) 47.402,32.578 47.402,32.924 R8.2 48.768,33.528 48.895,33.655 48.895,34.163 49.288,34.556 U4.23 ; v1(47.493,25.022) 47.586,25.022 47.721,24.887 U1.14
  Bottom Layer w0.254: v1(47.336,32.512) 47.336,25.272 47.493,25.115 v1(47.493,25.022)
IIC2_SDA: R9.2 U1.15 U4.24 | length 14
  Top Layer w0.254: v1(46.609,32.512) 46.609,33.401 R9.2 ; v1(46.675,24.953) 46.741,24.887 46.741,24.633 47.295,24.079 U1.15 ; v1(49.53,33.62) 49.596,33.686 49.596,33.832 49.804,34.04 49.804,34.056 U4.24
  Bottom Layer w0.254: v1(46.609,32.512) 46.642,32.479 46.642,24.986 v1(46.675,24.953) ; v1(47.117,33.909) 47.183,33.843 47.378,33.843 47.439,33.782 49.274,33.782 49.436,33.62 v1(49.53,33.62)
IIC_SCL: H1.4 R4.2 U1.42 | length 74.2
  Top Layer w0.254: v1(38.053,9.599) 40.25,9.599 v1(41.949,11.298) 42.043,11.298 42.175,11.43 R4.2 ; U1.42 54.178,17.704 54.864,17.018 57.15,17.018 59.055,15.113 v1(59.055,11.176)
  Bottom Layer w0.254: H1.4 28.69,36.31 27.94,35.56 27.94,16.764 35.052,9.652 38,9.652 v1(38.053,9.599) ; v1(41.949,11.298) 42.016,11.231 42.216,11.231 42.271,11.176 v1(59.055,11.176)
IIC_SDA: H1.3 R5.2 U1.43 | length 72.4
  Top Layer w0.254: v1(41.91,12.192) 42.828,13.11 43.209,13.11 R5.2 ; U1.43 56.339,17.526 57.15,17.526 59.563,15.113 v1@59.563,12.192
  Bottom Layer w0.254: H1.3 31.23,38.088 28.575,35.433 28.575,17.272 33.655,12.192 v1(41.91,12.192) 42.291,11.811 59.368,11.811 59.622,12.065 v1(59.69,12.065)
IO_N: U1.25
IO_P: U1.26
KEY_USB: C34.2 R28.1 R30.2 U1.51 | length 17.5
  Top Layer w0.254: U1.51 55.753,22.079 57.131,20.701 59.812,20.701 v1(61.463,19.05) ; R28.1 R30.2 v1(63.627,18.161)
  Bottom Layer w0.254: v1(61.463,19.05) 62.103,19.05 62.992,18.161 v1(63.627,18.161)
LED0: R3.1 U1.38 | length 40.4
  Top Layer w0.254: R3.1 32.639,5.715 33.909,6.985 v1(37.592,10.668) ; U1.38 52.578,17.526 53.594,16.51 57.15,16.51 58.547,15.113 58.547,11.684 57.531,10.668 v1(57.531,10.622)
  Bottom Layer w0.254: v1(37.592,10.668) 37.615,10.645 57.508,10.645 v1(57.531,10.622)
M1_A: U1.19 U3.1 | length 22.2
  Top Layer w0.254: v1(30.607,28.194) U3.1 ; v1(39.37,24.973) 39.705,24.638 45.085,24.638 47.244,22.479 U1.19
  Bottom Layer w0.254: v1(30.607,28.194) 30.607,28.1 30.771,27.936 30.771,27.903 33.701,24.973 v1(39.37,24.973)
M1_B: U1.52 U3.2 | length 30.6
  Top Layer w0.254: U3.2 31.877,28.321 32.131,28.067 v1(32.124,28.067) ; v1(40.894,28.829) 40.957,28.892 48.678,28.892 v1(48.741,28.956) ; v1(54.737,25.781) 54.737,24.586 54.425,24.274 54.425,22.685 54.603,22.506 54.959,22.506 U1.52
  Bottom Layer w0.254: v1(32.124,28.067) 36.195,28.067 36.957,28.829 v1(40.894,28.829) ; v1(48.741,28.956) 51.562,28.956 v1(54.737,25.781)
M1_C: U1.27 U3.3 | length 24.4
  Top Layer w0.254: U3.3 33.147,28.829 34.417,27.559 35.814,27.559 37.592,25.781 37.592,20.039 38.962,18.669 46.355,18.669 46.965,19.279 U1.27
M1_D: U1.13 U3.4 | length 18.5
  Top Layer w0.254: U3.4 34.417,28.829 35.242,28.003 36.005,28.003 38.354,25.654 49.154,25.654 49.351,25.457 49.351,24.914 U1.13
M2_A: U1.12 U3.5 | length 17.6
  Top Layer w0.254: U3.5 35.687,28.956 38.608,26.035 49.276,26.035 49.778,25.533 U1.12
M2_B: U1.11 U3.6 | length 17.2
  Top Layer w0.254: U3.6 36.957,28.448 38.989,26.416 49.53,26.416 50.178,25.768 U1.11
M2_C: U1.10 U3.7 | length 16.2
  Top Layer w0.254: U3.7 38.227,28.702 40.132,26.797 49.657,26.797 50.578,25.876 U1.10
M2_D: U1.9 U3.8 | length 15.2
  Top Layer w0.254: U3.8 39.497,29.083 41.367,27.213 49.749,27.213 50.978,25.984 U1.9
MPU_INT: R10.2 U4.12 | length 2.1
  Top Layer w0.254: U4.12 55.987,36.556 R10.2
NetA1_1: A1.1 U1.1 | length 2.7
  Top Layer w0.254: U1.1 54.178,27.532 A1.1
NetB1_2: B1.2 Q1.3 | length 3.3
  Top Layer w0.5: B1.2 24.755,40.572 Q1.3
NetC18_1: C18.1 U4.20 | length 2.1
  Top Layer w0.254: C18.1 50.058,36.068 U4.20
NetC19_2: C19.2 U4.10 | length 2.1
  Top Layer w0.254: U4.10 56.13,35.556 C19.2
NetC26_2: C26.2 U5.4 | length 3.4
  Top Layer w0.254: U5.4 31.623,13.462 32.385,12.7 C26.2
NetC29_1: C29.1 R24.2 R26.1 U8.5 | length 4.5
  Top Layer w0.3: U8.5 21.778,25.017 21.903,24.892 R26.1@23.495,24.892 ; R26.1 C29.1 R24.2
NetD1_2: D1.2 L3.2 U6.1
NetD2_2: D2.2 L4.2 U7.1
NetD4_2: D4.2 L5.2 U10.1
NetGND1_1: GND1.1 L2.2 P1.3 | length 6.1
  Top Layer w0.254: P1.3 45.08,6.091 L2.2
  Bottom Layer w0.254: GND1.1 P1.3
NetH1_2: H1.2 L1.2 | length 2.1
  Top Layer w0.5: H1.2 33.77,43.446 34.29,42.926 34.417,42.926 L1.2
NetH2_1: H2.1 U3.15 | length 14.5
  Top Layer w0.5: H2.1 22.873,44 23.423,43.45 26.781,43.45 27.559,42.672 32.893,42.672 34.406,41.159 34.406,39.635 U3.15
NetH2_2: H2.2 U3.16 | length 15.8
  Top Layer w0.5: H2.2 20.04,43.841 21.209,42.672 26.289,42.672 27.051,41.91 32.131,41.91 33.136,40.905 33.136,39.635 U3.16
NetH2_3: H2.3 U3.17 | length 16.8
  Top Layer w0.5: H2.3 19.59,41.91 25.781,41.91 26.543,41.148 31.369,41.148 31.866,40.651 31.866,39.635 U3.17
NetH2_4: H2.4 U3.18 | length 20
  Top Layer w0.5: H2.4 16.526,42.434 17.383,42.434 22.225,37.592 29.972,37.592 30.607,38.227 U3.18
NetH3_1: H3.1 U3.11 | length 18.6
  Top Layer w0.5: U3.11 39.497,38.227 40.132,37.592 48.26,37.592 52.52,41.852 52.52,43.94 H3.1
NetH3_2: H3.2 U3.12 | length 14.2
  Top Layer w0.5: U3.12 38.227,40.64 39.243,41.656 47.696,41.656 H3.2
NetH3_3: H3.3 U3.13 | length 13
  Top Layer w0.5: U3.13 36.968,39.635 36.968,40.651 38.989,42.672 46.172,42.672 H3.3
NetH3_4: H3.4 U3.14 | length 13.2
  Top Layer w0.5: U3.14 35.687,41.236 35.98,41.529 36.703,41.529 40.64,45.466 43.494,45.466 H3.4
NetL6_1: L6.1 U8.3
"NetLED 4_1": "LED 4.1" R22.2 | length 2.5
  Top Layer w0.3: 6.985,1.016 R22.2
"NetLED 4_2": "LED 4.2" U9.1 | length 11.7
  Top Layer w0.3: U9.1 6.162,10.983 v1(6.731,10.414) ; 8.255,1.016 v1(8.255,2.159)
  Bottom Layer w0.3: v1(6.731,10.414) 6.731,3.683 v1(8.255,2.159)
NetP3_2: P3.2 U9.3 U11.1 U11.2 | length 0.1
  Top Layer w0.3: P3.2 P3.2@3.495,9.21
NetQ2_1: Q2.1 R18.2 | length 2.5
  Top Layer w0.3: Q2.1 33.855,26.543 R18.2
NetQ3_1: Q3.1 R19.2 | length 5.9
  Top Layer w0.3: R19.2 31.882,26.548 33.025,26.548 v1(33.031,26.554) ; Q3.1 35.621,25.461 v1(36.195,26.035)
  Bottom Layer w0.3: v1(33.031,26.554) 34.406,26.554 34.925,26.035 v1(36.195,26.035)
NetR3_2: R3.2 SET.1 | length 1.1
  Top Layer w0.254: SET.1 R3.2
NetR6_2: R6.2 RXD.1@34.925,2.286 | length 1.1
  Top Layer w0.254: RXD.1@34.925,2.286 R6.2
NetR7_2: R7.2 TXD.1@37.338,2.286 | length 1.1
  Top Layer w0.254: TXD.1@37.338,2.286 R7.2
NetR12_1: R12.1 U5.2 | length 10.8
  Top Layer w0.254: U5.2 29.083,15.24 30.988,17.145 v1(32.258,17.145) ; v1(36.957,16.764) R12.1
  Bottom Layer w0.254: v1(32.258,17.145) 36.576,17.145 v1(36.957,16.764)
NetR13_1: R13.1 U5.3 | length 9.6
  Top Layer w0.254: U5.3 30.353,15.494 31.242,16.383 v1(32.258,16.383) ; v1(37.084,15.875) 37.465,15.494 R13.1
  Bottom Layer w0.254: v1(32.258,16.383) 32.431,16.21 36.749,16.21 v1(37.084,15.875)
NetR14_2: R14.2 R16.1 U6.3 | length 15.2
  Top Layer w0.3: R16.1 R14.2 1.52,20.07 1.647,20.07 2.159,19.558 2.667,19.558 6.096,16.129 6.096,14.478 v1(6.985,13.589) ; U6.3@10.038,14.102 U6.3 v1(10.414,13.462)
  Bottom Layer w0.3: v1(6.985,13.589) 10.287,13.589 v1(10.414,13.462)
NetR15_2: R15.2 R17.1 U7.3 | length 15
  Top Layer w0.3: R17.1 R15.2 2.286,33.909 2.794,33.909 6.159,30.543 6.159,28.892 6.604,28.448 v1(7.239,28.448) ; U7.3@10.292,28.961 U7.3 v1(10.795,28.321)
  Bottom Layer w0.3: v1(7.239,28.448) 7.366,28.321 v1(10.795,28.321)
NetR20_2: R20.2 USB1.A5 | length 10
  Top Layer w0.254: v1(51.532,7.756) 51.571,7.717 51.571,6.119 USB1.A5 ; v1(58.547,7.747) 58.613,7.681 58.994,7.681 R20.2
  Bottom Layer w0.254: v1(51.532,7.756) 58.538,7.756 v1(58.547,7.747)
NetR21_2: R21.2 USB1.B5 | length 6.4
  Top Layer w0.254: USB1.B5 54.594,7.096 55.88,8.382 R21.2@59.436,8.382
NetR23_1: R23.1 U9.5 | length 1.7
  Top Layer w0.3: R23.1 7.834,11.978 U9.5
NetR25_1: R25.1 R27.2 U10.3 | length 3.4
  Top Layer w0.3: U10.3 17.277,18.801 R27.2 17.653,20.593 R25.1
PWR_M1: 1.1 C20.2 D1.1 P2.2 POW.1 R14.1 | length 5.7
  Top Layer w0.3: R14.1 2.099,19.05 4.35,16.799 D1.1@4.35,15.113
PWR_M2: C16.1 C21.2 D2.1 H2.5 H3.5 R15.1 U3.10 | length 7.8
  Top Layer w0.3: R15.1 2.54,33.274 4.318,31.496 4.318,29.877 D2.1@4.35,29.845
  Top Layer w0.5: U3.10 43.38,39.624 C16.1
  other v1: 1.143,26.797 2.032,26.797 2.921,26.797 3.683,26.797 4.445,26.797 5.207,26.797 6.096,26.797 1.143,27.559 2.032,27.559 2.921,27.559 3.683,27.559 4.445,27.559 5.207,27.559 6.096,27.559 45.085,39.116 45.974,39.116 46.863,39.116 47.625,39.116 45.593,39.878 46.482,39.878 47.371,39.878 45.212,40.64 45.974,40.64 46.736,40.64 47.498,40.64
RTS: Q2.2 R19.1 U5.14 | length 6.3
  Top Layer w0.3: U5.14 30.287,20.465 Q2.2 30.607,25.2 R19.1
RXD: P1.1 RXD.1@40,2 RXD.2 U1.8 | length 64
  Top Layer w0.254: RXD.2 35.433,1.016 v1(36.195,1.778) ; P1.1 40,6.98 43.053,10.033 v1(44.831,10.033) ; U1.8 51.378,24.187 v1(51.435,24.13) ; v1(60.187,10.679) 60.244,10.735 60.244,16.81 62.865,19.431 62.865,24.892 v1(60.452,27.305)
  Bottom Layer w0.254: v1(36.195,1.778) 39.778,1.778 40,2 P1.1 ; v1(44.831,10.033) 59.542,10.033 v1(60.187,10.679) ; v1(51.435,24.13) 51.435,24.109 51.968,23.576 54.564,23.576 56.638,25.65 56.638,27.323 57.256,27.94 59.817,27.94 v1(60.452,27.305)
SPI2_CLK: U1.17
SPI2_MISO: U1.18
SPI2_MOSI: U1.16
SPICLK: U1.33 U2.6 | length 9.6
  Top Layer w0.254: U1.33 50.578,16.627 50.754,16.451 v1(50.754,16.358) ; U2.6 55.049,12.365 55.324,12.365 55.405,12.446 v1(55.498,12.446)
  Bottom Layer w0.254: v1(50.754,16.358) 51.999,15.113 54.102,15.113 55.499,13.716 v1(55.498,12.446)
SPICS0: U1.32 U2.1 | length 3.7
  Top Layer w0.254: U2.1 49.276,15.367 50.178,16.269 U1.32
SPID: U1.35 U2.5 | length 12
  Top Layer w0.254: U1.35 51.378,17.329 52.578,16.129 55.626,16.129 v1(56.007,15.748) ; U2.5 55.753,10.922 56.226,11.395 v1(56.226,12.58)
  Bottom Layer w0.254: v1(56.007,15.748) 56.007,15.654 56.226,15.435 v1(56.226,12.58)
SPIHD: U1.30 U2.7 | length 8.3
  Top Layer w0.254: v1(49.149,16.764) 49.149,16.891 49.378,17.12 U1.30
  Bottom Layer w0.254: v1(49.149,16.764) 49.149,16.002 51.192,13.959 v1(54.472,13.959)
SPIQ: U1.34 U2.2 | length 5.8
  Top Layer w0.254: U2.2 50.038,14.224 50.038,15.24 50.508,15.71 50.89,15.71 51.308,16.128 51.308,16.764 50.978,17.094 U1.34
SPIWP: U1.31 U2.3 | length 7.1
  Top Layer w0.254: U2.3 49.022,12.192 48.26,12.954 48.26,15.092 49.778,16.61 U1.31
TXD: P1.2 TXD.1@42.54,2 TXD.2 U1.6 | length 65.2
  Top Layer w0.254: TXD.2 38.354,2.032 38.354,2.921 39.116,3.683 41.223,3.683 P1.2 42.54,8.377 43.561,9.398 v1(45.212,9.398) ; U1.6 52.178,24.149 v1(52.197,24.13) ; v1(60.96,10.668) 60.96,16.764 63.5,19.304 63.5,25.4 v1(60.96,27.94)
  Bottom Layer w0.254: TXD.1@42.54,2 P1.2 ; v1(45.212,9.398) 59.69,9.398 v1(60.96,10.668) ; v1(52.197,24.13) 54.356,24.13 56.007,25.781 56.007,27.559 57.023,28.575 60.325,28.575 v1(60.96,27.94)
U0RXD: R12.2 U1.50 | length 29.6
  Top Layer w0.254: R12.2 40.193,16.195 40.701,16.195 v1(40.767,16.129) ; U1.50 55.532,21.679 56.865,20.345 59.665,20.345 60.452,19.558 v1(60.452,18.563)
  Bottom Layer w0.254: v1(40.767,16.129) 40.894,16.002 43.053,16.002 45.974,16.002 47.904,17.932 59.864,17.932 60.452,18.521 v1(60.452,18.563)
U0TXD: R13.2 U1.49 | length 27.7
  Top Layer w0.254: R13.2 41,15.494 42.05,16.545 v1(42.05,16.619) ; U1.49 55.429,21.279 56.718,19.99 59.004,19.99 59.69,19.304 v1(59.69,18.542)
  Bottom Layer w0.254: v1(42.05,16.619) 42.117,16.553 42.33,16.553 42.372,16.51 45.72,16.51 47.625,18.415 59.368,18.415 59.429,18.476 59.624,18.476 v1(59.69,18.542)
"USB 5V": C22.2 C23.2 C31.2 C32.2 D3.2 R22.1 R28.2 U5.16 U9.4 USB1.A4B9 USB1.B4A9 | length 53
  Top Layer w0.254: USB1.B4A9 55.244,6.857 55.626,7.239 57.658,7.239 58.674,6.223 62.064,6.223 62.357,6.516 R28.2
  Top Layer w0.3: U9.4 7.834,9.866 v1(7.874,9.906) ; R22.1 v1(8.255,4.572) ; v1@26.924,23.495 C22.2 ; U5.16 C22.2 ; C23.2 C22.2
  Bottom Layer w0.3: v1(8.255,4.572) 8.255,9.525 v1(7.874,9.906) 10.287,12.319 14.224,12.319 19.304,17.399 19.304,22.86 20.193,23.749 26.605,23.749 v1(26.855,23.5)
  other v1: 52.07,3.175 52.959,3.175 53.975,3.175 51.435,3.937 52.578,3.937 53.467,3.937 54.864,3.937 51.943,4.572 52.959,4.572 54.102,4.572 50.927,4.699 11.43,9.017 12.192,9.017 12.954,9.017 13.716,9.017 11.684,9.779 13.716,9.779 11.684,10.541 13.716,10.541 12.192,11.176 12.954,11.176 13.716,11.176
VDD_SPI: C12.2 C13.2 U1.29 U2.8 | length 11.7
  Top Layer w0.254: v1(48.392,17.378) 48.463,17.378 48.978,17.893 U1.29
  Top Layer w0.5: v1(54.864,15.575) 54.87,15.569 54.87,14.738 U2.8 C13.2 C12.2
  Bottom Layer w0.254: v1(48.392,17.378) 48.448,17.323 53.162,17.323 54.864,15.621 v1(54.864,15.575)
XH32_N: C9.2 U1.22 X2.2 | length 8
  Top Layer w0.254: X2.2 41.727,20.106 42.1,20.479 42.1,20.51 42.545,20.955 43.561,20.955 C9.2 45.212,20.066 46.425,21.279 U1.22
XH32_P: C8.2 U1.21 X2.1 | length 7.9
  Top Layer w0.254: X2.1 41.727,22.606 42.1,22.233 42.1,22.097 42.48,21.717 43.688,21.717 C8.2 45.323,22.495 46.139,21.679 U1.21
XH_N: C2.2 U1.53 X1.3 | length 8.3
  Top Layer w0.254: U1.53 56.242,22.879 C2.2 58.293,22.86 61.095,22.86 X1.3
XH_P: C1.2 U1.54 X1.1 | length 6.3
  Top Layer w0.254: U1.54 56.426,23.279 C1.2 58.039,23.368 59.563,23.368 X1.1
pads on no net: B1.3 U1.24 U1.28 U1.36 U1.37 U1.39 U1.40 U1.41 U1.44 U1.45 U1.47 U1.48 U4.2 U4.3 U4.4 U4.5 U4.14 U4.15 U4.16 U4.17 U4.19 U4.21 U4.22 U5.7 U5.8 U5.9 U5.10 U5.11 U5.12 U5.15 U6.6 U7.6 U10.6 USB1. USB1.A8 USB1.B8

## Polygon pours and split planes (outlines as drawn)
GND on Top Layer "GND_L01_P022" (solid, remove dead copper, pour order 22): 0,0 0,50 65,50 65,0
PWR_M2 on Top Layer "NONET_L-01_P-001" (solid, pour order 11): 0.381,26.416 7.239,26.416 8.001,27.178 8.001,28.448 7.747,28.702 6.985,28.702 6.985,29.21 5.334,30.861 0.381,30.861
"USB 5V" on Top Layer "NONET_L-01_P-001" (solid, pour order 20): 50.673,6.35 50.927,6.096 50.927,5.461 51.562,4.826 54.229,4.826 54.991,5.588 54.991,5.715 55.499,5.715 55.499,4.064 54.229,2.794 51.689,2.794 50.165,4.318 50.165,5.969
"USB 5V" on Top Layer "NONET_L-01_P-001" (solid, pour order 3): 8.128,9.271 8.509,9.652 10.554,9.652 12.205,11.444 14.097,11.444 14.097,8.509 8.382,8.509 8.001,8.89
NetL6_1 on Top Layer "NONET_L-01_P-001" (solid, pour order 18): 19.431,30.734 19.939,30.226 19.939,27.178 19.685,26.924 17.653,28.956 17.653,29.337
5V on Top Layer "NONET_L-01_P-001" (solid, pour order 17): 18.542,22.352 16.891,24.003 16.891,25.146 17.526,25.781 20.066,25.781 22.098,23.749 22.733,23.749 23.749,22.733 23.749,21.082 22.352,19.685 19.558,19.685 19.304,19.939 18.542,19.939
5V on Top Layer "NONET_L-01_P-001" (solid, pour order 15): 17.907,8.509 18.669,9.271 18.669,11.43 18.542,11.43 17.399,12.573 15.24,12.573 14.224,11.557 14.224,8.509
NetD4_2 on Top Layer "NONET_L-01_P-001" (solid, pour order 14): 18.923,18.034 20.32,19.431 22.733,19.431 24.765,21.463 26.67,21.463 26.67,17.145 26.162,16.637 18.923,16.637
NetD1_2 on Top Layer "NONET_L-01_P-001" (solid, pour order 7): 11.049,19.05 4.953,25.146 2.286,25.146 2.286,19.939 7.366,14.859 8.636,14.859 9.271,15.494 11.049,15.494
NetD2_2 on Top Layer "NONET_L-01_P-001" (solid, pour order 9): 5.08,39.751 11.43,33.401 11.43,30.48 11.303,30.353 9.525,30.353 8.89,29.718 8.89,28.956 7.366,28.956 2.54,33.782 2.54,39.624
BAT on Top Layer "NONET_L-01_P-001" (solid, pour order 8): 13.462,30.353 13.462,33.909 14.605,35.052 14.605,39.243 12.827,39.243 12.446,39.624 11.938,39.116 11.938,34.671 11.557,34.29 11.557,29.083 12.509,28.13 13.906,28.13 14.224,27.813
BAT on Top Layer "NONET_L-01_P-001" (solid, pour order 6): 13.208,15.24 12.319,15.24 12.192,15.367 12.192,16.51 15.367,19.685 15.367,27.051 17.018,28.702 17.018,30.353 12.7,30.353 12.446,30.099 12.446,28.702 13.589,27.559 13.589,26.289 12.065,24.765 12.065,19.177 11.176,18.288 11.176,14.478 11.811,13.843 14.097,13.843
BAT on Top Layer "NONET_L-01_P-001" (solid, pour order 4): 32.131,9.144 32.766,9.779 33.655,9.779 33.655,10.541 33.401,10.795 32.258,10.795 32.258,11.43 29.972,13.716 26.797,13.716 24.638,15.875 14.097,15.875 13.462,15.24 12.319,15.24 12.446,15.113 12.446,13.843 14.732,13.843 15.113,14.224 16.383,14.224 16.637,13.97 16.637,13.081 17.145,12.573 26.035,12.573 27.432,11.176 27.432,8.763 31.877,8.763 32.131,9.017
NetP3_2 on Top Layer "NONET_L-01_P-001" (solid, pour order 2): 4.572,10.033 4.572,9.652 4.699,9.525 6.096,9.525 7.112,8.509 17.907,8.509 18.669,9.271 18.669,11.43 19.685,12.446 26.162,12.446 27.432,11.176 27.432,8.763 25.273,6.604 4.572,6.604 2.54,8.636 2.54,10.033
PWR_M1 on Top Layer "NONET_L-01_P-001" (solid, remove dead copper, pour order 1): 5.207,16.002 0,16.002 0,0.127 -0.127,0 17.78,0 17.78,3.937 15.113,6.604 4.572,6.604 2.54,8.636 2.667,8.763 2.667,12.446 4.572,14.351 5.08,14.351
GND on Bottom Layer "GND_L02_P023" (solid, remove dead copper, pour order 23): 0,0 0,50 65,50 65,0
PWR_M2 on Bottom Layer "NONET_L-01_P-001" (solid, remove dead copper, pour order 13): 43.561,43.307 43.561,49.784 0.127,49.784 0.127,26.035 6.223,26.035 6.985,26.797 6.985,28.321 5.969,28.321 3.175,31.115 3.175,41.91 7.747,46.482 10.033,46.482 11.049,45.466 11.049,43.18 11.684,42.545 13.208,42.545 13.716,43.053 13.716,46.99 14.478,47.752 38.608,47.752 40.64,45.72 40.64,43.053 41.275,42.418 42.672,42.418
PWR_M2 on Bottom Layer "NONET_L-01_P-001" (solid, pour order 21): 40.64,43.688 40.64,39.878 42.164,38.354 48.133,38.354 48.133,41.148 46.863,42.418 44.45,42.418 43.561,43.307 43.561,43.815
"USB 5V" on Bottom Layer "NONET_L-01_P-001" (solid, pour order 19): 14.224,11.557 11.811,11.557 11.049,10.795 11.049,8.255 13.081,6.223 48.26,6.223 51.689,2.794 54.483,2.794 55.626,3.937 55.626,7.493 50.419,7.493 49.022,8.89 14.478,8.89 14.224,8.636
5V on Bottom Layer "NONET_L-01_P-001" (solid, pour order 16): 19.685,23.495 19.685,17.018 14.224,11.557 14.224,8.636 16.002,8.636 23.368,16.002 23.368,23.495
no net on Bottom Solder "NONET_L-01_P-001" (solid): 6.477,12.827 10.668,17.018 10.668,19.177 6.858,22.987
no net on Bottom Solder "NONET_L-01_P-001" (solid): 0.254,9.525 0.254,25.019 4.826,25.019 7.112,22.733 7.112,7.874 1.905,7.874

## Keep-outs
Keep-Out Layer:
  circle w0.1: c3,3 r2
  circle w0.1: c62,47 r1.25
  circle w0.1: c62,47 r2
  circle w0.1: c62,3 r1.25
  circle w0.1: c62,3 r2
  circle w0.1: c3,3 r1.25
  circle w0.1: c3,47 r1.25
  circle w0.1: c3,47 r2
  lines w0.1: 0,0 65,0 65,50 0,50 0,0

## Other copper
Top Layer:
  rectangle net PWR_M2: 42.418,38.354 48.006,41.148

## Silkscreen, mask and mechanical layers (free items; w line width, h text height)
Top Overlay:
  text "W-ROBOT-V1.0" at 45.847,40.407 h2
  text "2024.9.8" at 45.973,38.629 h2
  text "OFF" at 13.843,6.127 h3
  text "ON" at 32.004,5.746 h3
Bottom Overlay:
  text "SCL" at 28.805,42.363 h2 r90
  text "SDA" at 31.515,42.363 h2 r90
  text "GND" at 34.224,42.363 h2 r90
  text "VCC" at 36.935,42.363 h2 r90
  text "+ -" at 7.945,8.763 h3 r270
Top Solder:
  circle w1: c3,3 r1.5
  circle w1: c62,47 r1.5
  circle w1: c62,3 r1.5
  circle w1: c3,47 r1.5
Bottom Solder:
  circle w1: c3,3 r1.5
  circle w1: c62,47 r1.5
  circle w1: c62,3 r1.5
  circle w1: c3,47 r1.5

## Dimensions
1.75,46.877 to 4.25,47.123 on Mechanical 1
3,4.5 to 0,0 on Mechanical 1
0,50 to 65,50 on Mechanical 1
0,0 to 0,50 on Mechanical 1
